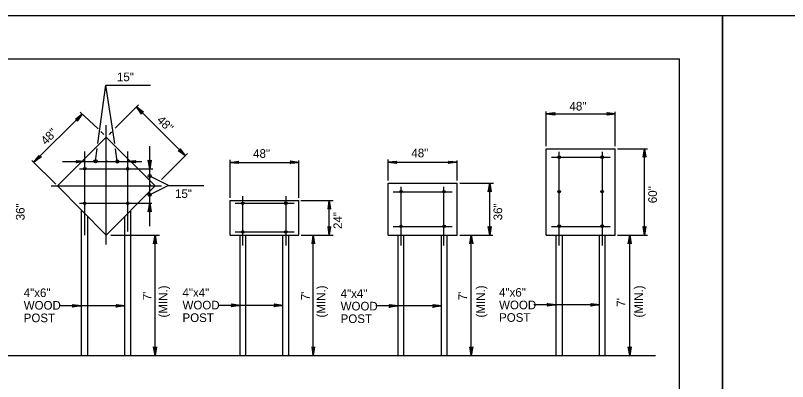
# Model space of a CAD drawing. Extents: x 648590 to 650336, y 294467 to 295061.
# Drawn here: x 649185.6 to 649453.6, y 294934.6 to 295061.4 of the extents above; entities that cross this region are included whole.
import ezdxf

# ---------------------------------------------------------------- set-up
doc = ezdxf.new("R2010")
doc.units = 0
for name, color, linetype in [('1', 7, 'Continuous'), ('2', 7, 'Continuous'), ('3', 7, 'Continuous'), ('PLT-BNDY', 7, 'Continuous')]:
    doc.layers.add(name, color=color, linetype=linetype)

msp = doc.modelspace()

# ---------------------------------------------------------------- linework, layer by layer
at = {"layer": '1'}
for p in [(648630.1, 295046.45), (649416.1, 294482.45)]:
    msp.add_line(p, (649416.1, 295046.45), dxfattribs=at)
at = {"layer": '2'}
for p, q in [((649214.2, 295017.12), (649217.03, 295037.3)), ((649217.03, 295037.3), (649232.5, 295037.3)), ((649228.33, 295030.45), (649220.29, 295022.41)), ((649244.5, 295012.87), (649227.62, 295029.74)), ((649192, 295010.57), (649208.82, 295027.27)), ((649208.12, 295027.98), (649214.32, 295022.13)), ((649369.85, 295016.09), (649369.85, 295028.14)), ((649369.85, 295027.39), (649393.85, 295027.39)), ((649393.85, 295016.09), (649393.85, 295028.01)), ((649215.28, 295021.22), (649216.35, 295020.22)), ((649217.1, 294982.09), (649217.1, 295023.4)), ((649200.22, 295002.34), (649217.1, 295019.22)), ((649234.1, 295002.34), (649217.1, 295019.22)), ((649218.98, 295021.11), (649218.1, 295020.22)), ((649232.23, 295002.17), (649232.23, 295016.14)), ((649209.72, 294985.34), (649209.72, 295014.34)), ((649213.42, 295010.9), (649213.97, 295015.32)), ((649224.6, 294986.59), (649224.6, 295014.34)), ((649245.33, 295013.62), (649236.35, 295004.64)), ((649369.85, 294985.34), (649369.85, 295015.22)), ((649369.85, 295015.22), (649393.85, 295015.22)), ((649374.35, 294981.72), (649374.35, 295014.22)), ((649389.35, 294981.72), (649389.35, 295014.22)), ((649393.85, 294985.34), (649393.85, 295015.22)), ((649394.6, 295015.22), (649405, 295015.22)), ((649404, 294985.34), (649404, 295015.22)), ((649199.6, 295002.97), (649191.34, 295011.23)), ((649202, 295010.84), (649217.1, 295010.84)), ((649216.85, 295010.47), (649217.47, 295011.22)), ((649217.1, 295010.84), (649229.49, 295010.84)), ((649260.1, 294998.22), (649260.1, 295011.39)), ((649260.1, 295010.52), (649283.97, 295010.52)), ((649283.97, 294998.22), (649283.97, 295011.14)), ((649314.97, 295004.22), (649314.97, 295011.48)), ((649314.97, 295010.61), (649338.97, 295010.61)), ((649338.97, 295004.22), (649338.97, 295011.23)), ((649371.72, 295012.34), (649392.1, 295012.34)), ((649374.35, 295012.34), (649374.35, 295012.34)), ((649389.35, 295012.34), (649389.35, 295012.34)), ((649207.85, 295008.34), (649233.34, 295008.34)), ((649238.79, 295002.52), (649232.22, 295005.79)), ((649231.9, 295002.07), (649232.65, 295002.69)), ((649238.79, 295002.52), (649232.22, 294999.28)), ((649238.79, 295002.52), (649251.03, 295002.52)), ((649314.97, 294985.34), (649314.97, 295003.34)), ((649314.97, 295003.34), (649338.97, 295003.34)), ((649338.97, 294985.34), (649338.97, 295003.34)), ((649339.85, 295003.34), (649351.51, 295003.34)), ((649350.26, 294985.34), (649350.26, 295003.34)), ((649197.97, 295002.34), (649236.35, 295002.34)), ((649217.1, 294985.34), (649200.22, 295002.34)), ((649217.1, 294985.34), (649234.1, 295002.34)), ((649232.23, 294988.4), (649232.23, 295002.17)), ((649316.72, 295000.34), (649337.22, 295000.34)), ((649319.47, 294981.72), (649319.47, 295002.09)), ((649319.47, 295000.34), (649319.47, 295000.34)), ((649334.35, 294981.72), (649334.35, 295002.09)), ((649334.35, 295000.34), (649334.35, 295000.34)), ((649374.35, 295000.34), (649374.35, 295000.34)), ((649389.35, 295000.34), (649389.35, 295000.34)), ((649260.1, 294985.34), (649260.1, 294997.34)), ((649260.1, 294997.34), (649283.97, 294997.34)), ((649264.6, 294981.72), (649264.6, 294998.84)), ((649279.6, 294981.72), (649279.6, 294998.84)), ((649283.97, 294985.34), (649283.97, 294997.34)), ((649284.72, 294997.34), (649295.86, 294997.34)), ((649284.85, 294997.34), (649290.1, 294997.34)), ((649294.5, 294985.34), (649294.5, 294997.34)), ((649207.85, 294996.34), (649233.01, 294996.34)), ((649261.85, 294996.34), (649282.35, 294996.34)), ((649264.6, 294996.34), (649264.6, 294996.34)), ((649279.6, 294996.34), (649279.6, 294996.34)), ((649208.6, 294943.59), (649208.6, 294993.84)), ((649210.72, 294943.59), (649210.72, 294991.84)), ((649223.6, 294943.59), (649223.6, 294991.84)), ((649225.72, 294943.59), (649225.72, 294993.84)), ((649261.85, 294986.47), (649282.35, 294986.47)), ((649264.6, 294986.47), (649264.6, 294986.47)), ((649279.6, 294986.47), (649279.6, 294986.47)), ((649316.72, 294988.34), (649337.22, 294988.34)), ((649319.47, 294988.34), (649319.47, 294988.34)), ((649334.35, 294988.34), (649334.35, 294988.34)), ((649371.72, 294988.34), (649392.1, 294988.34)), ((649374.35, 294988.34), (649374.35, 294988.34)), ((649389.35, 294988.34), (649389.35, 294988.34)), ((649218.72, 294985.34), (649235.6, 294985.34)), ((649234.1, 294943.59), (649234.1, 294985.34)), ((649260.1, 294985.34), (649283.97, 294985.34)), ((649263.6, 294943.59), (649263.6, 294985.34)), ((649265.6, 294943.59), (649265.6, 294985.34)), ((649278.47, 294943.59), (649278.47, 294985.34)), ((649280.47, 294943.59), (649280.47, 294985.34)), ((649284.85, 294985.34), (649295.86, 294985.34)), ((649288.97, 294943.59), (649288.97, 294985.34)), ((649314.97, 294985.34), (649338.97, 294985.34)), ((649318.47, 294943.59), (649318.47, 294985.34)), ((649320.47, 294943.59), (649320.47, 294985.34)), ((649333.47, 294943.59), (649333.47, 294985.34)), ((649335.47, 294943.59), (649335.47, 294985.34)), ((649339.85, 294985.34), (649351.38, 294985.34)), ((649343.85, 294943.59), (649343.85, 294985.34)), ((649369.85, 294985.34), (649393.85, 294985.34)), ((649373.35, 294943.59), (649373.35, 294985.34)), ((649375.47, 294943.59), (649375.47, 294985.34)), ((649388.35, 294943.59), (649388.35, 294985.34)), ((649390.35, 294943.59), (649390.35, 294985.34)), ((649394.6, 294985.34), (649405, 294985.34)), ((649398.85, 294943.59), (649398.85, 294985.34)), ((649223.6, 294960.79), (649200.79, 294960.79)), ((649278.47, 294960.95), (649255.93, 294960.95)), ((649333.47, 294960.75), (649310.72, 294960.75)), ((649388.35, 294961.13), (649365.57, 294961.13)), ((649039.22, 294943.59), (649407.82, 294943.59))]:
    msp.add_line(p, q, dxfattribs=at)
for points in [[(649220.16, 295017.02), (649217.03, 295037.3)], [(649229.37, 295027.49), (649229.5, 295027.74), (649227.62, 295029.74), (649229.37, 295027.49), (649229.37, 295027.24), (649227.62, 295029.74), (649229.62, 295027.87), (649229.87, 295027.99), (649227.62, 295029.74), (649230.12, 295027.99), (649229.87, 295027.99)], [(649206.57, 295025.52), (649206.7, 295025.52), (649208.82, 295027.27), (649206.57, 295025.52), (649206.45, 295025.52), (649208.82, 295027.27), (649206.95, 295025.27), (649207.07, 295025.02), (649208.82, 295027.27), (649207.07, 295024.77), (649207.07, 295025.02)], [(649372.85, 295027.01), (649372.72, 295027.26), (649369.85, 295027.39), (649372.85, 295027.01), (649372.85, 295026.89), (649369.85, 295027.39), (649372.72, 295027.39), (649372.85, 295027.64), (649369.85, 295027.39), (649372.85, 295027.76), (649372.85, 295027.64)], [(649390.97, 295027.64), (649390.97, 295027.39), (649393.85, 295027.39), (649390.97, 295027.64), (649390.85, 295027.76), (649393.85, 295027.39), (649390.97, 295027.26), (649390.97, 295027.01), (649393.85, 295027.39), (649390.85, 295026.89), (649390.97, 295027.01)], [(649220.97, 295010.84), (649220.4, 295015.2)], [(649242.87, 295014.99), (649242.75, 295014.87), (649244.5, 295012.87), (649242.87, 295014.99), (649242.75, 295015.24), (649244.5, 295012.87), (649242.5, 295014.62), (649242.37, 295014.49), (649244.5, 295012.87), (649242.12, 295014.49), (649242.37, 295014.49)], [(649403.63, 295012.47), (649403.88, 295012.59), (649404, 295015.22), (649403.63, 295012.47), (649403.5, 295012.34), (649404, 295015.22), (649404.13, 295012.59), (649404.38, 295012.47), (649404, 295015.22), (649404.5, 295012.34), (649404.38, 295012.47)], [(649194.37, 295012.44), (649194.12, 295012.44), (649192, 295010.57), (649194.37, 295012.44), (649194.62, 295012.44), (649192, 295010.57), (649194, 295012.57), (649193.87, 295012.82), (649192, 295010.57), (649193.87, 295012.94), (649193.87, 295012.82)], [(649206.85, 295011.09), (649206.97, 295010.97), (649209.72, 295010.84), (649206.85, 295011.09), (649206.72, 295011.22), (649209.72, 295010.84), (649206.97, 295010.72), (649206.97, 295010.59), (649209.72, 295010.84), (649206.72, 295010.34), (649206.97, 295010.59)], [(649227.35, 295010.47), (649227.22, 295010.72), (649224.6, 295010.84), (649227.35, 295010.47), (649227.47, 295010.34), (649224.6, 295010.84), (649227.22, 295010.84), (649227.35, 295011.09), (649224.6, 295010.84), (649227.47, 295011.22), (649227.35, 295011.09)], [(649232.6, 295011.22), (649232.35, 295011.09), (649232.23, 295008.34), (649232.6, 295011.22), (649232.73, 295011.34), (649232.23, 295008.34), (649231.98, 295011.09), (649231.85, 295011.22), (649232.23, 295008.34), (649231.73, 295011.34), (649231.85, 295011.22)], [(649262.97, 295010.27), (649262.85, 295010.39), (649260.1, 295010.52), (649262.97, 295010.27), (649263.1, 295010.14), (649260.1, 295010.52), (649262.85, 295010.64), (649262.97, 295010.77), (649260.1, 295010.52), (649263.1, 295010.89), (649262.97, 295010.77)], [(649281.1, 295010.89), (649281.22, 295010.64), (649283.97, 295010.52), (649281.1, 295010.89), (649280.97, 295011.02), (649283.97, 295010.52), (649281.22, 295010.39), (649281.22, 295010.27), (649283.97, 295010.52), (649280.97, 295010.14), (649281.22, 295010.27)], [(649317.85, 295010.23), (649317.72, 295010.48), (649314.97, 295010.61), (649317.85, 295010.23), (649317.97, 295010.11), (649314.97, 295010.61), (649317.72, 295010.61), (649317.85, 295010.86), (649314.97, 295010.61), (649317.97, 295010.98), (649317.85, 295010.86)], [(649336.1, 295010.86), (649336.22, 295010.73), (649338.97, 295010.61), (649336.1, 295010.86), (649335.97, 295010.98), (649338.97, 295010.61), (649336.22, 295010.48), (649336.1, 295010.36), (649338.97, 295010.61), (649335.97, 295010.11), (649336.1, 295010.36)], [(649349.88, 295000.47), (649350.13, 295000.59), (649350.26, 295003.34), (649349.88, 295000.47), (649349.76, 295000.34), (649350.26, 295003.34), (649350.38, 295000.59), (649350.63, 295000.47), (649350.26, 295003.34), (649350.76, 295000.34), (649350.63, 295000.47)], [(649294.25, 294994.47), (649294.38, 294994.59), (649294.5, 294997.34), (649294.25, 294994.47), (649294.13, 294994.34), (649294.5, 294997.34), (649294.63, 294994.59), (649294.88, 294994.47), (649294.5, 294997.34), (649295, 294994.34), (649294.88, 294994.47)], [(649231.85, 294993.47), (649231.98, 294993.59), (649232.23, 294996.34), (649231.85, 294993.47), (649231.73, 294993.34), (649232.23, 294996.34), (649232.35, 294993.59), (649232.48, 294993.47), (649232.23, 294996.34), (649232.73, 294993.34), (649232.48, 294993.47)], [(649294.88, 294988.22), (649294.63, 294988.09), (649294.5, 294985.34), (649294.88, 294988.22), (649295, 294988.34), (649294.5, 294985.34), (649294.38, 294988.09), (649294.25, 294988.22), (649294.5, 294985.34), (649294.13, 294988.34), (649294.25, 294988.22)], [(649350.63, 294988.22), (649350.51, 294988.09), (649350.26, 294985.34), (649350.63, 294988.22), (649350.76, 294988.34), (649350.26, 294985.34), (649350.13, 294988.09), (649349.88, 294988.22), (649350.26, 294985.34), (649349.76, 294988.34), (649349.88, 294988.22)], [(649404.38, 294988.22), (649404.13, 294988.09), (649404, 294985.34), (649404.38, 294988.22), (649404.5, 294988.34), (649404, 294985.34), (649403.88, 294988.09), (649403.63, 294988.22), (649404, 294985.34), (649403.5, 294988.34), (649403.63, 294988.22)], [(649233.72, 294982.59), (649233.97, 294982.72), (649234.1, 294985.34), (649233.72, 294982.59), (649233.6, 294982.34), (649234.1, 294985.34), (649234.22, 294982.72), (649234.47, 294982.59), (649234.1, 294985.34), (649234.6, 294982.34), (649234.47, 294982.59)], [(649288.72, 294982.59), (649288.85, 294982.72), (649288.97, 294985.34), (649288.72, 294982.59), (649288.6, 294982.34), (649288.97, 294985.34), (649289.1, 294982.72), (649289.35, 294982.59), (649288.97, 294985.34), (649289.47, 294982.34), (649289.35, 294982.59)], [(649343.47, 294982.59), (649343.72, 294982.72), (649343.85, 294985.34), (649343.47, 294982.59), (649343.35, 294982.34), (649343.85, 294985.34), (649343.97, 294982.72), (649344.22, 294982.59), (649343.85, 294985.34), (649344.35, 294982.34), (649344.22, 294982.59)], [(649398.47, 294982.59), (649398.72, 294982.72), (649398.85, 294985.34), (649398.47, 294982.59), (649398.35, 294982.34), (649398.85, 294985.34), (649398.97, 294982.72), (649399.22, 294982.59), (649398.85, 294985.34), (649399.35, 294982.34), (649399.22, 294982.59)], [(649205.59, 294961.17), (649205.71, 294961.04), (649208.46, 294960.79), (649205.59, 294961.17), (649205.46, 294961.29), (649208.46, 294960.79), (649205.71, 294960.67), (649205.59, 294960.54), (649208.46, 294960.79), (649205.46, 294960.29), (649205.59, 294960.54)], [(649220.72, 294961.17), (649220.85, 294961.04), (649223.6, 294960.79), (649220.72, 294961.17), (649220.6, 294961.29), (649223.6, 294960.79), (649220.85, 294960.67), (649220.72, 294960.54), (649223.6, 294960.79), (649220.6, 294960.29), (649220.72, 294960.54)], [(649260.73, 294961.33), (649260.85, 294961.2), (649263.6, 294960.95), (649260.73, 294961.33), (649260.6, 294961.45), (649263.6, 294960.95), (649260.85, 294960.83), (649260.73, 294960.7), (649263.6, 294960.95), (649260.6, 294960.45), (649260.73, 294960.7)], [(649275.6, 294961.33), (649275.72, 294961.2), (649278.47, 294960.95), (649275.6, 294961.33), (649275.47, 294961.45), (649278.47, 294960.95), (649275.72, 294960.83), (649275.6, 294960.7), (649278.47, 294960.95), (649275.47, 294960.45), (649275.6, 294960.7)], [(649315.52, 294961.13), (649315.65, 294961), (649318.4, 294960.75), (649315.52, 294961.13), (649315.4, 294961.25), (649318.4, 294960.75), (649315.65, 294960.63), (649315.52, 294960.5), (649318.4, 294960.75), (649315.4, 294960.25), (649315.52, 294960.5)], [(649330.6, 294961.13), (649330.72, 294961), (649333.47, 294960.75), (649330.6, 294961.13), (649330.47, 294961.25), (649333.47, 294960.75), (649330.72, 294960.63), (649330.6, 294960.5), (649333.47, 294960.75), (649330.47, 294960.25), (649330.6, 294960.5)], [(649370.37, 294961.51), (649370.49, 294961.38), (649373.24, 294961.13), (649370.37, 294961.51), (649370.24, 294961.63), (649373.24, 294961.13), (649370.49, 294961.01), (649370.37, 294960.88), (649373.24, 294961.13), (649370.24, 294960.63), (649370.37, 294960.88)], [(649385.47, 294961.51), (649385.6, 294961.38), (649388.35, 294961.13), (649385.47, 294961.51), (649385.35, 294961.63), (649388.35, 294961.13), (649385.6, 294961.01), (649385.47, 294960.88), (649388.35, 294961.13), (649385.35, 294960.63), (649385.47, 294960.88)], [(649234.47, 294946.34), (649234.22, 294946.22), (649234.1, 294943.59), (649234.47, 294946.34), (649234.6, 294946.59), (649234.1, 294943.59), (649233.97, 294946.22), (649233.72, 294946.34), (649234.1, 294943.59), (649233.6, 294946.59), (649233.72, 294946.34)], [(649289.35, 294946.34), (649289.1, 294946.22), (649288.97, 294943.59), (649289.35, 294946.34), (649289.47, 294946.59), (649288.97, 294943.59), (649288.85, 294946.22), (649288.72, 294946.34), (649288.97, 294943.59), (649288.6, 294946.59), (649288.72, 294946.34)], [(649344.22, 294946.34), (649344.1, 294946.22), (649343.85, 294943.59), (649344.22, 294946.34), (649344.35, 294946.59), (649343.85, 294943.59), (649343.72, 294946.22), (649343.47, 294946.34), (649343.85, 294943.59), (649343.35, 294946.59), (649343.47, 294946.34)], [(649399.22, 294946.34), (649398.97, 294946.22), (649398.85, 294943.59), (649399.22, 294946.34), (649399.35, 294946.59), (649398.85, 294943.59), (649398.72, 294946.22), (649398.47, 294946.34), (649398.85, 294943.59), (649398.35, 294946.59), (649398.47, 294946.34)]]:
    msp.add_lwpolyline(points, dxfattribs=at)
for centre, radius in [((649213.42, 295010.9), 0.55), ((649220.97, 295010.84), 0.55), ((649374.37, 295012.31), 0.441), ((649389.26, 295012.31), 0.441), ((649209.68, 295008.31), 0.441), ((649224.59, 295008.29), 0.441), ((649232.22, 295005.79), 0.55), ((649232.22, 294999.28), 0.55), ((649319.48, 295000.35), 0.441), ((649334.37, 295000.37), 0.441), ((649374.34, 295000.35), 0.441), ((649389.26, 295000.35), 0.441), ((649209.64, 294996.32), 0.441), ((649224.59, 294996.35), 0.441), ((649264.53, 294996.32), 0.441), ((649279.46, 294996.38), 0.441), ((649264.53, 294986.42), 0.441), ((649279.45, 294986.38), 0.441), ((649319.46, 294988.38), 0.441), ((649334.44, 294988.35), 0.441), ((649374.34, 294988.43), 0.441), ((649389.32, 294988.43), 0.441)]:
    msp.add_circle(centre, radius, dxfattribs=at)
at = {"layer": '3'}
for p, q in [((649209.72, 295008.34), (649209.72, 295008.34)), ((649224.6, 295008.34), (649224.6, 295008.34)), ((649209.72, 294996.34), (649209.72, 294996.34)), ((649224.6, 294996.34), (649224.6, 294996.34))]:
    msp.add_line(p, q, dxfattribs=at)
at = {"layer": 'PLT-BNDY'}
for points in [[(648590.1, 295061.45), (649431.1, 295061.45), (649431.1, 294467.45), (648590.1, 294467.45)], [(649431.1, 295061.45), (650272.1, 295061.45), (650272.1, 294467.45), (649431.1, 294467.45)]]:
    msp.add_lwpolyline(points, close=True, dxfattribs=at)

# ---------------------------------------------------------------- texts
at = {"layer": '3'}
for s, height, p in [('15"', 3, (649220.85, 295038.66)), ('48"', 3, (649377.94, 295028.5)), ('48"', 3, (649268.12, 295012.1)), ('48"', 3, (649323.06, 295012.27)), ('15"', 3, (649241, 294998.2)), ('4"x6"', 2.988, (649188.5, 294963.85)), ('4"x4"', 2.988, (649243.62, 294963.93)), ('4"x4"', 2.988, (649298.51, 294963.57)), ('4"x6"', 2.988, (649353.51, 294963.99)), ('WOOD', 2.988, (649188.5, 294959.49)), ('WOOD', 2.988, (649243.62, 294959.56)), ('WOOD', 2.988, (649298.51, 294959.2)), ('WOOD', 2.988, (649353.51, 294959.62)), ('POST', 2.988, (649188.5, 294955.13)), ('POST', 2.988, (649243.62, 294955.2)), ('POST', 2.988, (649298.51, 294954.84)), ('POST', 2.988, (649353.51, 294955.26))]:
    msp.add_text(s, height=height, dxfattribs=at).set_placement(p)
for s, rotation, p in [('48"', 315, (649234.5, 295024.93)), ('48"', 45, (649196.21, 295016.36)), ('60"', 90, (649408.28, 294996.37)), ('36"', 90, (649188.79, 294990.43)), ('36"', 90, (649354.58, 294990.43)), ('24"', 90, (649299.02, 294987.43)), ('(MIN.)', 90, (649238.37, 294956.73)), ('(MIN.)', 90, (649293.2, 294956.73)), ('(MIN.)', 90, (649348.57, 294956.73)), ('(MIN.)', 90, (649403.43, 294956.73)), ("7'", 90, (649232.85, 294962.73)), ("7'", 90, (649287.79, 294962.73)), ("7'", 90, (649342.33, 294962.73)), ("7' ", 90, (649397.36, 294960.47))]:
    msp.add_text(s, height=3, rotation=rotation, dxfattribs=at).set_placement(p)

doc.saveas('drawing.dxf')
